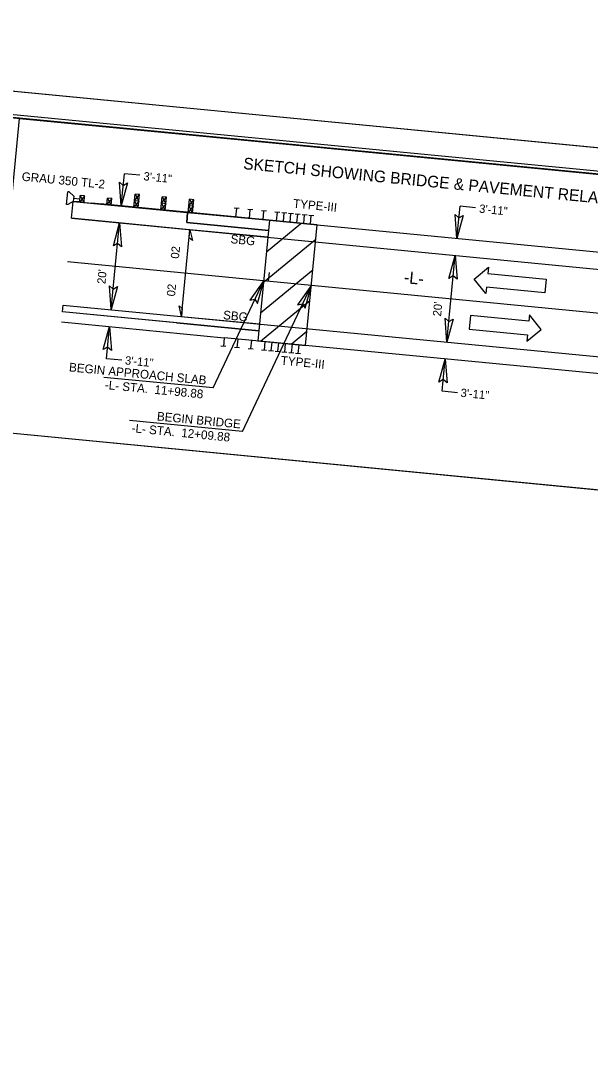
# Model space of a CAD drawing. Extents: x 2060525 to 2062119, y 912110 to 913300.
# Drawn here: x 2061170.5 to 2061366.5, y 912602.5 to 912962.2 of the extents above; entities that cross this region are included whole.
import ezdxf

# ---------------------------------------------------------------- set-up
doc = ezdxf.new("R2010")
doc.units = 0
for name, color, linetype in [('Default', 7, 'Continuous'), ('Prop Approach Slab', 7, 'Continuous'), ('Prop Approach Slab Hatching', 7, 'Continuous'), ('Prop Conc Shoulder Berm Gutter', 7, 'Continuous'), ('Prop DGN Element Guardrail', 7, 'Continuous'), ('Prop Dimension', 7, 'Continuous'), ('Prop Dimension Text', 7, 'Continuous'), ('Prop EOT', 7, 'Continuous'), ('Prop Guardrail', 7, 'Continuous'), ('Prop Guardrail Anchor Unit CELL', 7, 'Continuous'), ('Prop Horizontal Alignment', 7, 'Continuous'), ('Prop Horizontal Alignment Station Label', 7, 'Continuous'), ('Prop Horizontal Alignment Tick Label', 7, 'Continuous'), ('Prop Horizontal Alignment Tick Small', 7, 'Continuous'), ('Prop Lane Arrow CELL', 7, 'Continuous'), ('Prop Paved Shoulder', 7, 'Continuous'), ('Prop Roadway Bridge', 7, 'Continuous'), ('Prop Shade Medium', 7, 'Continuous'), ('Prop Structure Anchor Unit CELL', 7, 'Continuous'), ('Prop Superelevation  Arrow CELL', 7, 'Continuous'), ('Prop Superelevation Label', 7, 'Continuous'), ('Prop Terminator CELL', 7, 'Continuous'), ('Sheet Clip Boundary CELL', 7, 'Continuous'), ('Sheet Cutting Line CELL', 7, 'Continuous'), ('Sheet Layout Plan Border', 7, 'Continuous'), ('Sheet Plan CELL', 7, 'Continuous'), ('Sheet Plan Layout CELL', 7, 'Continuous'), ('Sheet Plot Border Inside CELL', 7, 'Continuous'), ('Sheet Plot Border Outside CELL', 7, 'Continuous')]:
    doc.layers.add(name, color=color, linetype=linetype)

msp = doc.modelspace()

# ---------------------------------------------------------------- linework, layer by layer
at = {"layer": 'Prop Approach Slab'}
for p, q in [((2061256.15, 912893.53), (2061252.13, 912851.97)), ((2061256.15, 912893.53), (2061272.57, 912891.94)), ((2061252.13, 912851.97), (2061268.56, 912850.38))]:
    msp.add_line(p, q, dxfattribs=at)
at = {"layer": 'Prop Approach Slab Hatching'}
for p, q in [((2061255.11, 912882.72), (2061266.96, 912892.48)), ((2061254.08, 912872.16), (2061272.1, 912887)), ((2061253.06, 912861.61), (2061271.08, 912876.44)), ((2061253.05, 912851.88), (2061270.05, 912865.88)), ((2061263.61, 912850.86), (2061269.03, 912855.33))]:
    msp.add_line(p, q, dxfattribs=at)
at = {"layer": 'Prop Conc Shoulder Berm Gutter'}
for p, q in [((2061227.96, 912896.25), (2061256.15, 912893.53)), ((2061224.28, 912858.18), (2061252.47, 912855.45))]:
    msp.add_line(p, q, dxfattribs=at)
at = {"layer": 'Prop DGN Element Guardrail'}
msp.add_line((2061272.57, 912891.94), (2061197.92, 912899.15), dxfattribs=at)
at = {"layer": 'Prop Dimension'}
for p, q in [((2061205.11, 912898.46), (2061206.18, 912909.55)), ((2061211.49, 912909.04), (2061206.18, 912909.55)), ((2061320.66, 912887.29), (2061321.74, 912898.38)), ((2061327.05, 912897.87), (2061321.74, 912898.38)), ((2061201.66, 912862.75), (2061204.54, 912892.61)), ((2061317.21, 912851.58), (2061320.1, 912881.44)), ((2061236.7, 912835.76), (2061254.14, 912872.75)), ((2061246.82, 912820.81), (2061270.56, 912871.16)), ((2061200.02, 912845.81), (2061201.09, 912856.9)), ((2061205.33, 912845.3), (2061200.02, 912845.81)), ((2061315.58, 912834.64), (2061316.65, 912845.73)), ((2061236.7, 912835.76), (2061199.1, 912839.4)), ((2061320.89, 912834.13), (2061315.58, 912834.64)), ((2061246.82, 912820.81), (2061207.98, 912824.56))]:
    msp.add_line(p, q, dxfattribs=at)
at = {"layer": 'Prop EOT'}
for p, q in [((2061188.02, 912894.21), (2061463.86, 912867.55)), ((2061185.14, 912864.35), (2061460.98, 912837.68))]:
    msp.add_line(p, q, dxfattribs=at)
at = {"layer": 'Prop Guardrail'}
for p, q in [((2061244.58, 912894.64), (2061235.25, 912895.55)), ((2061184.57, 912858.5), (2061240.56, 912853.09))]:
    msp.add_line(p, q, dxfattribs=at)
at = {"layer": 'Prop Guardrail Anchor Unit CELL'}
for p, q in [((2061186.25, 912898.99), (2061186.68, 912903.38)), ((2061187.14, 912903.33), (2061186.68, 912903.38)), ((2061187.14, 912903.33), (2061188.77, 912901.88)), ((2061188.77, 912901.88), (2061188.59, 912900.06)), ((2061190.78, 912899.83), (2061191, 912902.09)), ((2061192.5, 912901.95), (2061190.78, 912899.83)), ((2061192.5, 912901.95), (2061191, 912902.09)), ((2061192.28, 912899.68), (2061191, 912902.09)), ((2061192.28, 912899.68), (2061192.5, 912901.95)), ((2061209.45, 912898.02), (2061209.89, 912902.55)), ((2061209.67, 912900.29), (2061211.38, 912902.41)), ((2061211.38, 912902.41), (2061209.89, 912902.55)), ((2061209.89, 912902.55), (2061211.16, 912900.14)), ((2061210.94, 912897.88), (2061211.38, 912902.41)), ((2061218.78, 912897.12), (2061219.22, 912901.65)), ((2061219, 912899.39), (2061220.71, 912901.51)), ((2061220.71, 912901.51), (2061219.22, 912901.65)), ((2061219.22, 912901.65), (2061220.49, 912899.24)), ((2061220.27, 912896.97), (2061220.71, 912901.51)), ((2061186.71, 912898.94), (2061186.25, 912898.99)), ((2061188.59, 912900.06), (2061186.71, 912898.94)), ((2061190.79, 912899.84), (2061188.59, 912900.06)), ((2061188.7, 912901.13), (2061190.89, 912900.91)), ((2061192.28, 912899.68), (2061190.78, 912899.83)), ((2061191.53, 912899.75), (2061228.86, 912896.14)), ((2061200.12, 912898.92), (2061200.34, 912901.19)), ((2061201.83, 912901.05), (2061200.12, 912898.92)), ((2061201.61, 912898.78), (2061200.12, 912898.92)), ((2061201.61, 912898.78), (2061200.33, 912901.19)), ((2061201.83, 912901.05), (2061200.34, 912901.19)), ((2061201.61, 912898.78), (2061201.83, 912901.05)), ((2061211.16, 912900.14), (2061209.45, 912898.02)), ((2061210.94, 912897.88), (2061209.45, 912898.02)), ((2061211.16, 912900.14), (2061209.67, 912900.29)), ((2061210.94, 912897.88), (2061209.67, 912900.29)), ((2061220.49, 912899.24), (2061218.78, 912897.12)), ((2061220.49, 912899.24), (2061219, 912899.39)), ((2061220.27, 912896.97), (2061219, 912899.39)), ((2061228.11, 912896.22), (2061228.55, 912900.75)), ((2061229.82, 912898.34), (2061228.11, 912896.22)), ((2061228.33, 912898.48), (2061230.04, 912900.6)), ((2061229.82, 912898.34), (2061228.33, 912898.48)), ((2061229.6, 912896.07), (2061228.33, 912898.48)), ((2061230.04, 912900.6), (2061228.55, 912900.75)), ((2061228.55, 912900.75), (2061229.82, 912898.34)), ((2061229.6, 912896.07), (2061230.04, 912900.6)), ((2061220.27, 912896.97), (2061218.78, 912897.12)), ((2061229.6, 912896.07), (2061228.11, 912896.22))]:
    msp.add_line(p, q, dxfattribs=at)
at = {"layer": 'Prop Horizontal Alignment'}
msp.add_line((2061186.58, 912879.28), (2061462.42, 912852.61), dxfattribs=at)
at = {"layer": 'Prop Horizontal Alignment Tick Small'}
msp.add_line((2061255.81, 912872.59), (2061256.1, 912875.57), dxfattribs=at)
at = {"layer": 'Prop Lane Arrow CELL'}
for p, q in [((2061326.55, 912873.21), (2061331.5, 912877.36)), ((2061331.5, 912877.36), (2061331.3, 912875.21)), ((2061330.63, 912868.33), (2061326.55, 912873.21)), ((2061331.3, 912875.21), (2061351.36, 912873.27)), ((2061351.36, 912873.27), (2061350.9, 912868.54)), ((2061330.84, 912870.48), (2061330.63, 912868.33)), ((2061350.9, 912868.54), (2061330.84, 912870.48)), ((2061325.34, 912860.72), (2061324.88, 912855.99)), ((2061345.4, 912858.78), (2061325.34, 912860.72)), ((2061345.61, 912860.93), (2061345.4, 912858.78)), ((2061349.68, 912855.91), (2061345.61, 912860.93)), ((2061324.88, 912855.99), (2061344.95, 912854.05)), ((2061344.74, 912851.9), (2061349.68, 912855.91)), ((2061344.95, 912854.05), (2061344.74, 912851.9))]:
    msp.add_line(p, q, dxfattribs=at)
at = {"layer": 'Prop Paved Shoulder'}
for p, q in [((2061227.96, 912896.25), (2061227.96, 912896.25)), ((2061256.15, 912893.53), (2061272.57, 912891.94)), ((2061252.13, 912851.97), (2061268.56, 912850.38))]:
    msp.add_line(p, q, dxfattribs=at)
for points in [[(2061255.81, 912890.04), (2061227.62, 912892.77), (2061227.96, 912896.25), (2061194.98, 912899.46)], [(2061252.47, 912855.45), (2061184.91, 912861.98)]]:
    msp.add_lwpolyline(points, dxfattribs=at)
at = {"layer": 'Prop Roadway Bridge'}
for p, q in [((2061268.56, 912850.38), (2061272.57, 912891.94)), ((2061272.57, 912891.94), (2061380.45, 912881.51)), ((2061376.43, 912839.95), (2061268.56, 912850.38))]:
    msp.add_line(p, q, dxfattribs=at)
at = {"layer": 'Prop Shade Medium'}
for points in [[(2061188.02, 912894.21), (2061188.59, 912900.06), (2061227.96, 912896.25), (2061227.62, 912892.77), (2061255.81, 912890.04), (2061255.58, 912887.68), (2061227.4, 912890.4)], [(2061252.7, 912857.82), (2061252.47, 912855.45), (2061224.28, 912858.18), (2061184.91, 912861.98), (2061185.14, 912864.35), (2061224.51, 912860.54)]]:
    msp.add_lwpolyline(points, close=True, dxfattribs=at)
at = {"layer": 'Prop Structure Anchor Unit CELL'}
for p, q in [((2061245.72, 912897.55), (2061244.01, 912897.71)), ((2061244.58, 912894.64), (2061244.87, 912897.63)), ((2061272.57, 912891.94), (2061244.58, 912894.64)), ((2061250.39, 912897.1), (2061248.68, 912897.26)), ((2061249.24, 912894.19), (2061249.53, 912897.18)), ((2061255.05, 912896.65), (2061253.34, 912896.81)), ((2061253.91, 912893.74), (2061254.2, 912896.73)), ((2061259.72, 912896.19), (2061258.01, 912896.36)), ((2061258.58, 912893.29), (2061258.86, 912896.28)), ((2061262.05, 912895.97), (2061260.34, 912896.13)), ((2061260.91, 912893.07), (2061261.2, 912896.05)), ((2061264.39, 912895.74), (2061262.68, 912895.91)), ((2061263.24, 912892.84), (2061263.53, 912895.83)), ((2061266.72, 912895.52), (2061265.01, 912895.68)), ((2061265.57, 912892.62), (2061265.86, 912895.6)), ((2061269.05, 912895.29), (2061267.34, 912895.46)), ((2061267.91, 912892.39), (2061268.2, 912895.38)), ((2061271.38, 912895.07), (2061269.67, 912895.23)), ((2061270.24, 912892.16), (2061270.53, 912895.15)), ((2061240.56, 912853.09), (2061240.27, 912850.1)), ((2061268.56, 912850.38), (2061240.56, 912853.09)), ((2061245.23, 912852.64), (2061244.94, 912849.65)), ((2061249.89, 912852.19), (2061249.6, 912849.2)), ((2061254.56, 912851.74), (2061254.27, 912848.75)), ((2061256.89, 912851.51), (2061256.6, 912848.52)), ((2061259.22, 912851.28), (2061258.94, 912848.3)), ((2061261.56, 912851.06), (2061261.27, 912848.07)), ((2061241.13, 912850.02), (2061239.42, 912850.18)), ((2061245.79, 912849.57), (2061244.08, 912849.73)), ((2061250.46, 912849.12), (2061248.75, 912849.28)), ((2061255.13, 912848.67), (2061253.42, 912848.83)), ((2061257.46, 912848.44), (2061255.75, 912848.61)), ((2061259.79, 912848.22), (2061258.08, 912848.38)), ((2061262.12, 912847.99), (2061260.41, 912848.16)), ((2061264.46, 912847.76), (2061262.75, 912847.93)), ((2061263.89, 912850.83), (2061263.6, 912847.85)), ((2061266.79, 912847.54), (2061265.08, 912847.7)), ((2061266.22, 912850.61), (2061265.93, 912847.62))]:
    msp.add_line(p, q, dxfattribs=at)
at = {"layer": 'Prop Superelevation  Arrow CELL'}
msp.add_line((2061225.83, 912860.41), (2061228.72, 912890.28), dxfattribs=at)
for points in [[(2061228.72, 912890.28), (2061229.57, 912886.58), (2061228.45, 912887.51)], [(2061225.83, 912860.41), (2061224.98, 912864.11), (2061226.1, 912863.18)]]:
    msp.add_lwpolyline(points, close=True, dxfattribs=at)
at = {"layer": 'Prop Terminator CELL'}
for points in [[(2061207.28, 912906.39), (2061205.11, 912898.46), (2061204.46, 912906.71), (2061205.79, 912905.54)], [(2061322.83, 912895.22), (2061320.66, 912887.29), (2061320.01, 912895.54), (2061321.35, 912894.37)], [(2061202.38, 912884.68), (2061204.54, 912892.61), (2061205.19, 912884.37), (2061203.86, 912885.54)], [(2061317.93, 912873.51), (2061320.1, 912881.44), (2061320.75, 912873.2), (2061319.42, 912874.37)], [(2061251.95, 912864.83), (2061254.14, 912872.75), (2061249.36, 912866), (2061251.11, 912866.32)], [(2061203.83, 912870.68), (2061201.66, 912862.75), (2061201.01, 912871), (2061202.34, 912869.83)], [(2061268.37, 912863.24), (2061270.56, 912871.16), (2061265.79, 912864.41), (2061267.53, 912864.73)], [(2061319.38, 912859.51), (2061317.21, 912851.58), (2061316.56, 912859.83), (2061317.9, 912858.66)], [(2061198.92, 912848.98), (2061201.09, 912856.9), (2061201.74, 912848.66), (2061200.41, 912849.83)], [(2061314.48, 912837.81), (2061316.65, 912845.73), (2061317.3, 912837.49), (2061315.96, 912838.66)]]:
    msp.add_lwpolyline(points, close=True, dxfattribs=at)
at = {"layer": 'Sheet Clip Boundary CELL'}
msp.add_lwpolyline([(2060947.75, 912528.18), (2061534.24, 912471.49), (2061175.38, 912506.18), (2061182.37, 912578.54), (2061543.72, 912543.62), (2061569, 912805.1), (2061475.51, 912814.14), (2061473.23, 912790.55), (2061159.65, 912820.86), (2061167, 912896.82), (2061010.06, 912911.99), (2061013.14, 912943.82), (2060988.16, 912946.23)], close=True, dxfattribs=at)
at = {"layer": 'Sheet Cutting Line CELL'}
msp.add_line((2061586.54, 912897.43), (2060916.27, 912962.22), dxfattribs=at)
at = {"layer": 'Sheet Layout Plan Border'}
msp.add_lwpolyline([(2060947.75, 912528.18), (2061530.76, 912471.83), (2061563.03, 912805.68), (2061475.51, 912814.14), (2061483.65, 912898.34), (2060988.16, 912946.23)], close=True, dxfattribs=at)
at = {"layer": 'Sheet Plan CELL'}
for points in [[(2061578.92, 912889.13), (2060981.69, 912946.86), (2060941.28, 912528.81), (2061538.5, 912471.08)], [(2060941.28, 912528.81), (2060981.68, 912946.85), (2061499.26, 912896.83), (2061493.49, 912837.09), (2061573.14, 912829.38), (2061538.5, 912471.08)], [(2061170.06, 912928.65), (2061483.65, 912898.34), (2061473.22, 912790.47), (2061159.65, 912820.86)]]:
    msp.add_lwpolyline(points, close=True, dxfattribs=at)
at = {"layer": 'Sheet Plan Layout CELL'}
msp.add_lwpolyline([(2060981.68, 912946.85), (2060941.28, 912528.81), (2061538.5, 912471.08), (2061570.77, 912804.93), (2061475.51, 912814.14), (2061483.65, 912898.34)], close=True, dxfattribs=at)
at = {"layer": 'Sheet Plot Border Inside CELL'}
msp.add_lwpolyline([(2060880.07, 912533.71), (2061543.38, 912469.6), (2061583.98, 912889.64), (2060920.68, 912953.76)], close=True, dxfattribs=at)
at = {"layer": 'Sheet Plot Border Outside CELL'}
msp.add_lwpolyline([(2060874.13, 912526.25), (2061544.4, 912461.46), (2061586.54, 912897.43), (2060916.27, 912962.22)], close=True, dxfattribs=at)

# ---------------------------------------------------------------- texts
at = {"layer": 'Default'}
for p in [(2061242.62, 912885.66), (2061240.05, 912859.49)]:
    msp.add_text('SBG', height=3, rotation=354.4787, dxfattribs=at).set_placement(p)
at = {"layer": 'Prop Dimension Text'}
for s, height, rotation, p in [('3\'-11"', 2.88, 354.4787, (2061212.64, 912907.34)), ('3\'-11"', 2.88, 354.4787, (2061328.2, 912896.17)), ("20'", 2.88, 84.4787, (2061199.63, 912871.47)), ("20'", 2.88, 84.4787, (2061315.19, 912860.3)), ('BEGIN APPROACH SLAB', 3, 354.4787, (2061187.01, 912841.51)), ('3\'-11"', 2.88, 354.4787, (2061206.27, 912843.91)), ('-L- STA.  11+98.88', 3, 354.4787, (2061199.34, 912835.42)), ('3\'-11"', 2.88, 354.4787, (2061321.82, 912832.74)), ('BEGIN BRIDGE', 3, 354.4787, (2061217.28, 912824.6)), ('-L- STA.  12+09.88', 3, 354.4787, (2061208.57, 912820.55))]:
    msp.add_text(s, height=height, rotation=rotation, dxfattribs=at).set_placement(p)
at = {"layer": 'Prop Guardrail Anchor Unit CELL'}
msp.add_text('GRAU 350 TL-2', height=3, rotation=354.4787, dxfattribs=at).set_placement((2061170.72, 912907.19))
at = {"layer": 'Prop Horizontal Alignment Station Label'}
msp.add_text('SKETCH SHOWING BRIDGE & PAVEMENT RELATIONSHIP', height=4, rotation=354.4787, dxfattribs=at).set_placement((2061246.96, 912911.19))
at = {"layer": 'Prop Horizontal Alignment Tick Label'}
msp.add_text('-L-', height=4.2, rotation=354.4787, dxfattribs=at).set_placement((2061302.24, 912871.91))
at = {"layer": 'Prop Structure Anchor Unit CELL'}
for p in [(2061264.15, 912897.89), (2061259.9, 912843.84)]:
    msp.add_text('TYPE-III', height=3, rotation=354.4787, dxfattribs=at).set_placement(p)
at = {"layer": 'Prop Superelevation Label'}
for p in [(2061224.95, 912880.2), (2061223.59, 912867.22)]:
    msp.add_text('02', height=2.88, rotation=84.4787, dxfattribs=at).set_placement(p)

doc.saveas('drawing.dxf')
